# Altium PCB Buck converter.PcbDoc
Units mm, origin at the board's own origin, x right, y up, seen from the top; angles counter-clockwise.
Board outline 85.72 x 66.93 mm, 2 copper layers (Top Layer, Bottom Layer); 24 components, 13 nets, 75 pads, 15 vias.
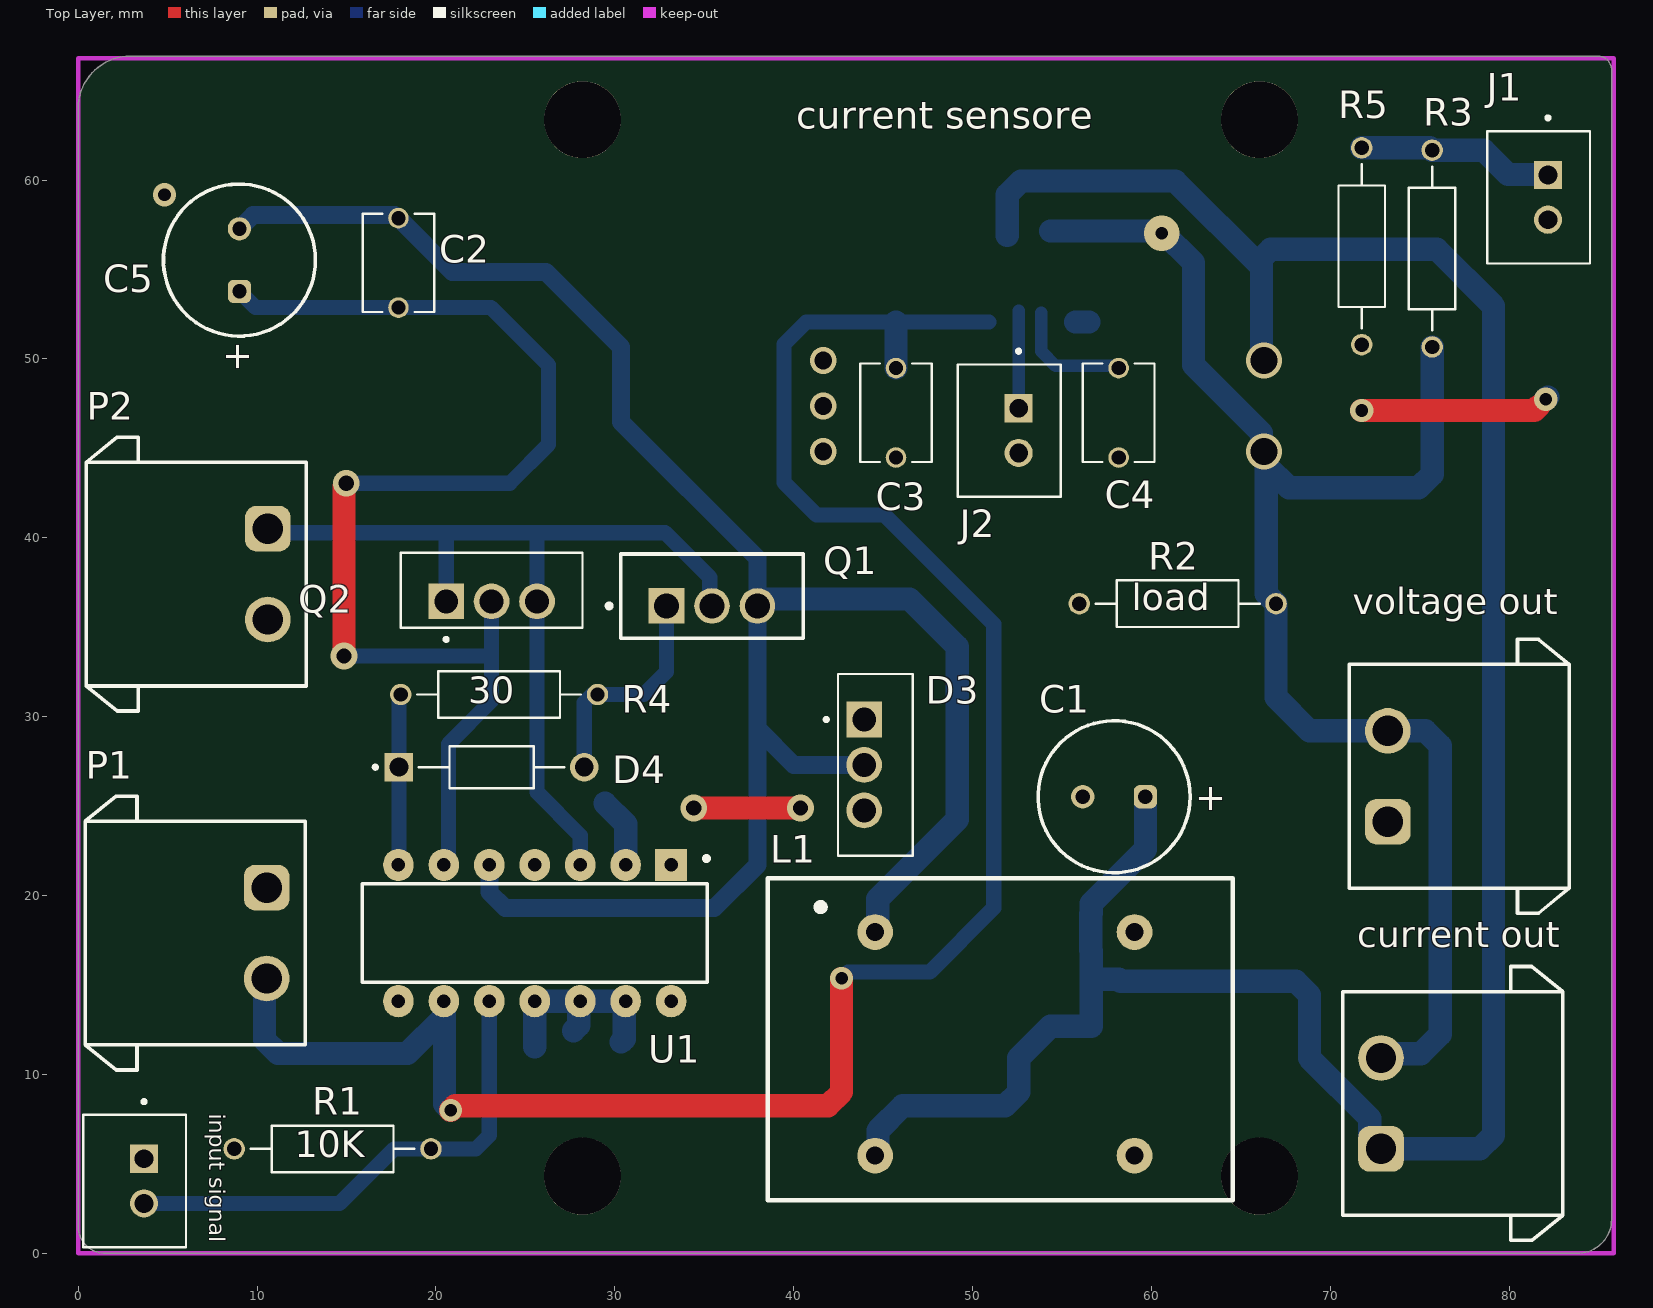
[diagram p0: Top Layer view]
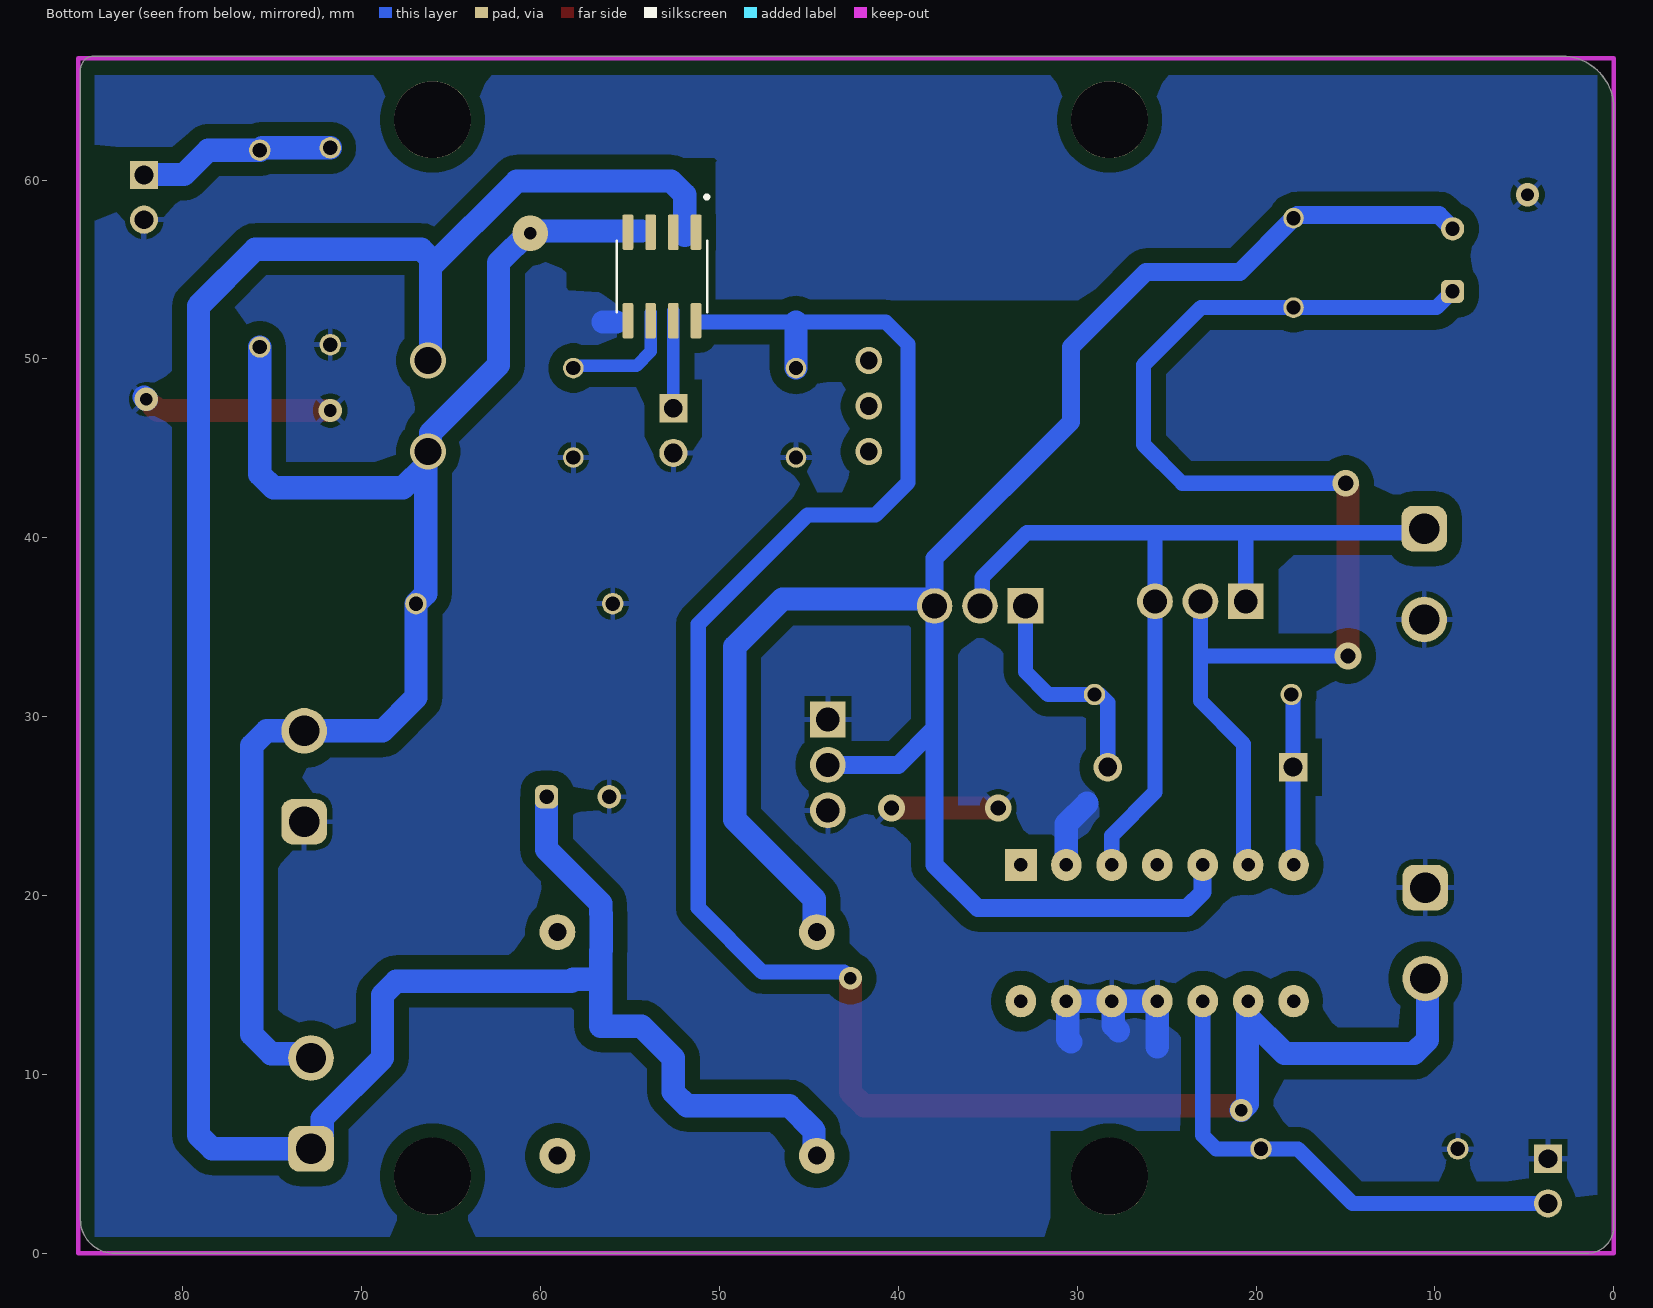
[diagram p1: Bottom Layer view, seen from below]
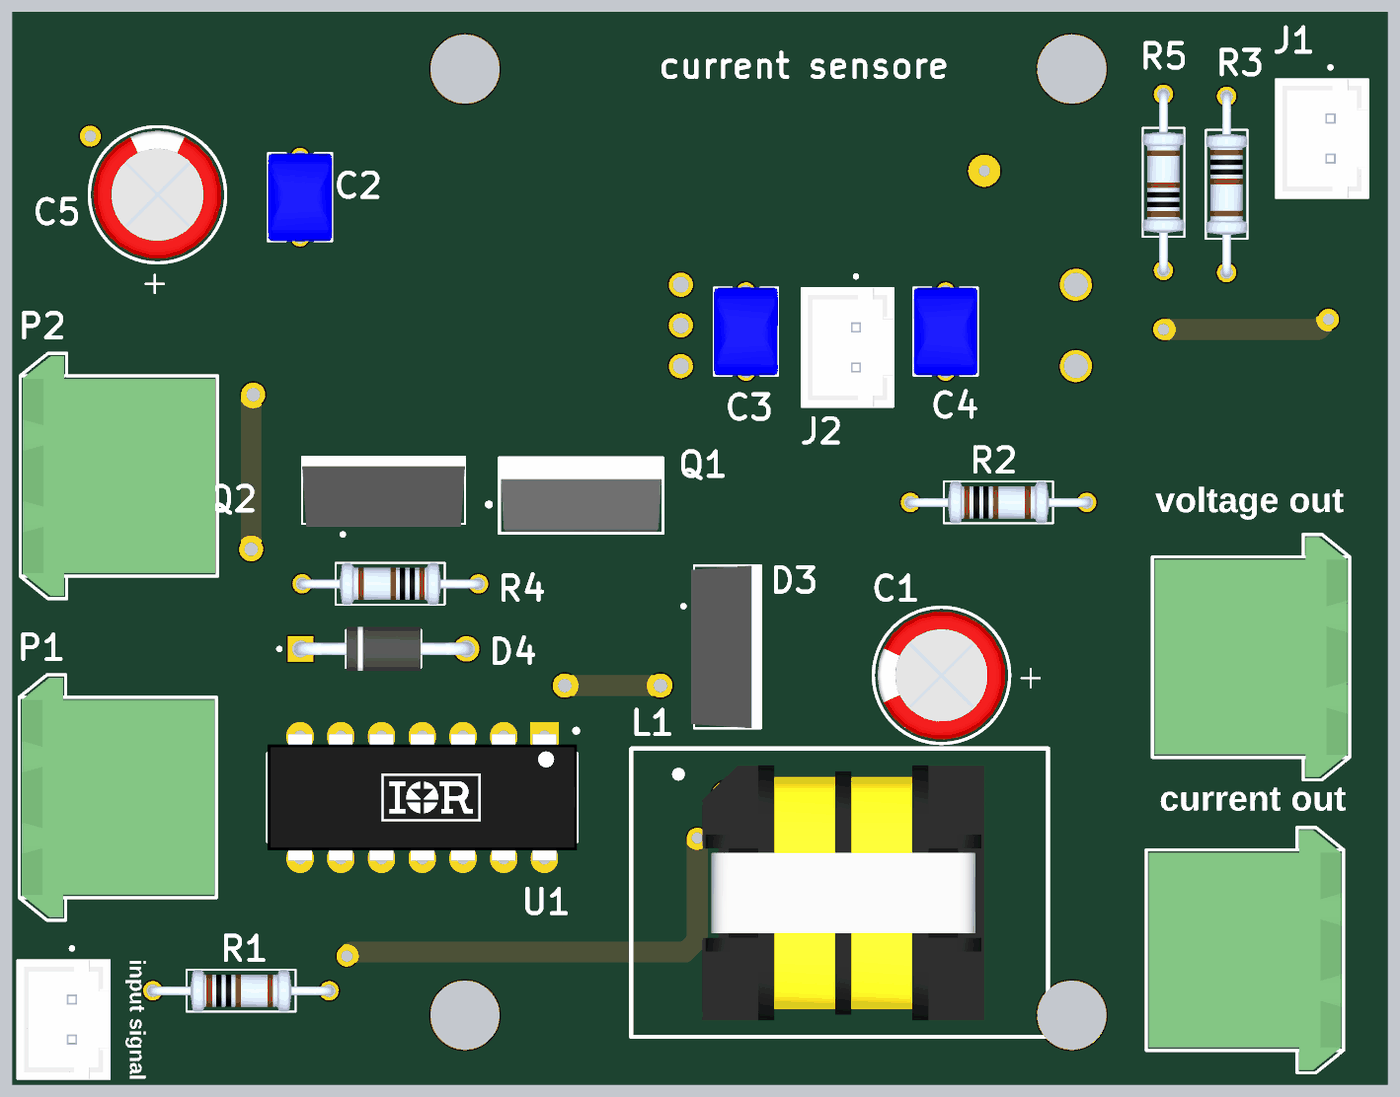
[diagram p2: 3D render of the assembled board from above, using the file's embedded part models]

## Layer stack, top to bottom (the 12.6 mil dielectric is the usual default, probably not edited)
Top Solder: solder mask 0.0102, Solder Resist, Dk 3.5
Top Layer: signal copper 0.0356
Dielectric 1: dielectric 0.32, FR-4, Dk 4.8
Bottom Layer: signal copper 0.0356
Bottom Solder: solder mask 0.0102, Solder Resist, Dk 3.5

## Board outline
0,1.524 0,64.008 cw(c2.921,64.008) 2.921,66.929 84.963,66.929 cw(c84.963,66.167) 85.725,66.167 85.725,1.905 cw(c83.82,1.905) 83.82,0 1.524,0 cw(c1.524,1.524)

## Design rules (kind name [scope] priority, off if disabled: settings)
Clearance [All] p1: gap=0.8 ignorepadtopadclearanceinfootprint=FALSE
PolygonConnect PolygonConnect_6 [All vs IsNamedPolygon('NONET_L-01_P-001')] p1: thpad.connectstyle=Relief thpad.reliefconductorwidth=0.3 thpad.reliefentries=4 thpad.polygonreliefangle="90 Angle" thpad.airgapwidth=0.3 smdpad.connectstyle=Relief smdpad.reliefconductorwidth=0.3 smdpad.reliefentries=4 smdpad.polygonreliefangle="45 Angle" smdpad.airgapwidth=0.3 via.connectstyle=Relief via.reliefconductorwidth=0.3 via.reliefentries=4 via.polygonreliefangle="45 Angle" via.airgapwidth=0.3
PolygonConnect PolygonConnect_5 [All vs IsNamedPolygon('NONET_L-01_P-001')] p2: thpad.connectstyle=Relief thpad.reliefconductorwidth=0.3 thpad.reliefentries=4 thpad.polygonreliefangle="45 Angle" thpad.airgapwidth=0.254 smdpad.connectstyle=Relief smdpad.reliefconductorwidth=0.254 smdpad.reliefentries=4 smdpad.polygonreliefangle="90 Angle" smdpad.airgapwidth=0.254 via.connectstyle=Relief via.reliefconductorwidth=0.254 via.reliefentries=4 via.polygonreliefangle="90 Angle" via.airgapwidth=0.254
PolygonConnect PolygonConnect_4 [All vs IsNamedPolygon('NONET_L-01_P-001')] p3: connectstyle=Relief reliefconductorwidth=0.254 reliefentries=4 polygonreliefangle="90 Angle" airgapwidth=0.15
PolygonConnect PolygonConnect_3 [All vs IsNamedPolygon('NONET_L-01_P-001')] p4: connectstyle=Relief reliefconductorwidth=0.254 reliefentries=4 polygonreliefangle="90 Angle" airgapwidth=0.254
PolygonConnect PolygonConnect_2 [All vs IsNamedPolygon('NONET_L-01_P-001')] p5: connectstyle=Direct reliefconductorwidth=0.254 reliefentries=4 polygonreliefangle="90 Angle" airgapwidth=0.254
PolygonConnect PolygonConnect_1 [All vs IsNamedPolygon('GND_L02_P000')] p6: connectstyle=Direct reliefconductorwidth=0.254 reliefentries=4 polygonreliefangle="90 Angle" airgapwidth=0.254
PolygonConnect [All] p7: connectstyle=Relief reliefconductorwidth=0.254 reliefentries=4 polygonreliefangle="90 Angle" airgapwidth=0.254
RoutingVias [All] p1: holewidth=0.711 width=1.27 viastyle="Through Hole" minholewidth=0.711 minwidth=1.27 maxholewidth=0.711 maxwidth=1.27
SolderMaskExpansion [All] p1: expansion=0.102 istentingtop=FALSE
SupplyNets "Schematic Supply Nets_10" [InNet('+5')] p1: voltage=0.000
SupplyNets "Schematic Supply Nets_9" [InNet('VCC')] p2: voltage=0.000
SupplyNets "Schematic Supply Nets_8" [InNet('GND')] p3: voltage=0.000
Width [All] p1: maxlimit=1.5 minlimit=1.2 preferedwidth=1.3 minimp=50.000000 maximp=50.000000 favimp=50.000000
30 further rules are at their usual default settings.

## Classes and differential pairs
component class "Buck converter": C1 C2 C3 C4 C5 "current out" D3 D4 "input signal" J1 L1 P1 P2 Q1 Q2 R1 R2 R3 R4 R5 U1 "voltage out"

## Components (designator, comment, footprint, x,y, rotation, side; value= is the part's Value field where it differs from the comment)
C1 "22uf cap" "cap 22uf 50V" 57.912,25.527 r0 top
C2 "cap 0.1uf" "CAP ceramic" 17.907,55.372 r90 top
C3 "cap 100nf" "CAP ceramic" 45.72,46.99 r90 top
C4 "cap 1nf" "CAP ceramic" 58.166,46.99 r270 top
C5 "220uf cap" "cap 22uf 50V" 9.017,55.527 r270 top
"current out" "691305540002" "Horizontal Pluggable" 76.835,8.382 r90 top
D3 "MBR20100CT" TO254P1066X482X2286-3 43.942,29.845 r270 top
D4 "1N5820" 1N4007 23.114,27.178 r0 top
"input signal" "JST_B2B vertical pins" "JST_B2B vertical pins" 3.158,4.044 r90 top
J1 "JST_B2B vertical pins" "JST_B2B vertical pins" 81.644,59.035 r90 top (schematic designator J?)
J2 "JST_B2B vertical pins" "JST_B2B vertical pins" 52.053,45.994 r90 top (schematic designator J?)
L1 "2mH E shape" "2mH E shape" 44.555,17.961 r0 top value=2mH
P1 "691305540002" "Horizontal Pluggable" 6.541,17.907 r270 top
P2 "691305540002" "Horizontal Pluggable" 6.604,37.973 r270 top
Q1 "IRLZ44N" IFX-PG-TO220-3-904-1 35.433,36.195 r0 top
Q2 "U10A6CIC" TO254P1066X482X2286-3 20.574,36.449 r0 top
R1 "10k" RES 14.224,5.842 r0 top
R2 "load" RES 61.468,36.322 r0 top
R3 "30K" RES 75.692,56.173 r270 top
R4 "30" RES 23.534,31.242 r180 top
R5 "7.5K" RES 71.755,56.3 r90 top
U1 "IR2110" DIP762W46P254L1930H533Q14B 25.527,17.907 r270 top
U2 "ACS712" SOIC127P600X175-8N 53.213,54.61 r270 bottom
"voltage out" "691305540002" "Horizontal Pluggable" 77.216,26.67 r90 top

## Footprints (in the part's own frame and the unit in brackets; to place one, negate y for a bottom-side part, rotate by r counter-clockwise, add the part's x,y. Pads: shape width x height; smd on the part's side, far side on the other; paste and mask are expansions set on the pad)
1N4007 [mm]
  round 1.59 hole 1.06 mask+0.102: A(5.18,0)
  rect 1.59x1.59 / inner round 1.59 / far side rect 1.59x1.59 hole 1.06 mask+0.102: C(-5.18,0)
  silkscreen extent -6.6,-1.17 4.07,1.17, body extent -5.57,-1.36 5.57,1.36, height 2.72
"2mH E shape" [mm]
  round 2 hole 1: 1(0,0) 2(0,-12.5) 3(14.5,0) 4(14.5,-12.5)
  silkscreen extent -6,-15 20,3, body extent -1.56,-13.97 16.04,1.93, height 18.9
"cap 22uf 50V" [mm] "Aluminum Electrolytic Capacitors, 8x11.5mm"
  rrect50% 1.3x1.3 hole 0.8: 1(1.75,0)
  round 1.3 hole 0.8: 2(-1.75,0)
  silkscreen extent -4.25,-4.25 4.25,4.25, body extent -3.99,-4 4,4, height 11.81
"CAP ceramic" [mm]
  round 1.15 hole 0.8: 1(-2.5,0) 2(2.5,0)
  silkscreen extent -2.75,-2 2.75,2, body extent -2.75,-2 2.75,2, height 7
DIP762W46P254L1930H533Q14B [mm] "DIP,7.62mm lead span,2.54mm pitch;14 pin,6.605mm W X 19.305mm L X 5.33mm H body"
  rect 1.8x1.8 hole 0.75 paste-2539.97 mask+0: 1(-3.81,7.62)
  oval 1.8x1.7 hole 0.75 paste-2539.97 mask+0: 2(-3.81,5.08) 3(-3.81,2.54) 4(-3.81,0) 5(-3.81,-2.54) 6(-3.81,-5.08) 7(-3.81,-7.62) 8(3.81,-7.62) 9(3.81,-5.08) 10(3.81,-2.54) 11(3.81,0) 12(3.81,2.54) 13(3.81,5.08) 14(3.81,7.62)
  silkscreen extent -4.29,-9.65 2.75,9.73, body extent -3.96,-9.65 3.96,9.65, height 5.33
"Horizontal Pluggable" [mm] "5,08mm - PCB Header Horizontal Entry with Plastic Latches - 02p"
  rrect50% 2.55x2.55 hole 1.7: 1(-2.54,4)
  round 2.55 hole 1.7: 2(2.54,4)
  silkscreen extent -7.65,-6.15 7.65,6.15, body extent -7.48,-6 7.48,6, height 8.63
IFX-PG-TO220-3-904-1 [mm] "TO,flange mount,2.54 mm pitch, 3 pin, 10.16 mm L X 4.57 mm W X 20.56 mm H body"
  rect 1.99x1.99 hole 1.39 paste-2539.97 mask+0: 1(-2.54,0)
  round 1.99 hole 1.39 paste-2539.97 mask+0: 2(0,0) 3(2.54,0)
  silkscreen extent -5.87,-1.8 5.1,2.9, body extent -5.16,-1.72 5.16,2.86, height 19.84
"JST_B2B vertical pins" [mm]
  rect 1.575x1.575 / inner round 1.575 / far side rect 1.575x1.575 hole 1.05: 1(1.25,-0.525)
  round 1.575 hole 1.05: 2(-1.25,-0.525)
  silkscreen extent -3.7,-2.88 4.54,2.88, body extent -3.7,-2.88 3.7,2.88, height 7
RES [mm]
  round 1.2 hole 0.8: 1(-5.5,0) 2(5.5,0)
  silkscreen extent -4.58,-1.3 4.58,1.3, body extent -5.77,-1.3 5.77,1.3, height 2.6
SOIC127P600X175-8N [mm]
  rrect25% 1.97x0.6 smd paste+0 mask+0.102: 1(-2.475,1.905) 2(-2.475,0.635) 3(-2.475,-0.635) 4(-2.475,-1.905) 5(2.475,-1.905) 6(2.475,-0.635) 7(2.475,0.635) 8(2.475,1.905)
  silkscreen extent -4.54,-2.52 2,2.6, body extent -3,-2.45 3,2.45, height 1.75
TO254P1066X482X2286-3 [mm]
  rect 2x2 / inner round 2 / far side rect 2x2 hole 1.33: 1(0,0)
  round 2 hole 1.33: 2(2.54,0) 3(5.08,0)
  silkscreen extent -2.54,-2.22 7.62,2.72, body extent -2.54,-1.65 7.62,2.7, height 20.4

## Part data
C1: "CAP ALUM 22UF 20% 400V RADIAL", Package="RADIAL-2 Panasonic"
C2 C3 C4: library part "cap 100nF", "Capacitor, Ceramic, 100nF, 100VDC, 10-% Tol, 10+% Tol, X7R-TC Code, -15, 15%-TC", Package="Radial AVX"
C5: library part "22uf cap", "CAP ALUM 22UF 20% 400V RADIAL", Package="RADIAL-2 Panasonic"
"current out" P1 P2 "voltage out": library part "horizontal Pluggable", "WR-TBL Series 3055 PCB Header Horizontal Entry with Plastic Latches, THT, pitch 5.08mm, 2p", Manufacturer="Wurth Elektronik", Operating Temperature Max=105°C, Operating Temperature Min=-40°C, Rated Current=16A, Working Voltage=300V
D3: "Diode Array 1 Pair Common Cathode Schottky 100 V 10A Through Hole TO-262-3 Long Leads, IÂ²Pak, TO-262AA", Package="TO-220-3 ON Semiconductor"
D4: library part 1N4007, "Diode, DO-41, 1000V, 1A, 175Â°C", Package="DO-41 Diotec"
"input signal" J1 J2: "Connector Header Through Hole 2 position 0.098 (2.50mm)", Package=None
L1: library part CMP-006-00023-3
Q1: "OptiMOS 3 Power-Transistor, VDS 100V", Manufacturer="Infineon Technologies"
Q2: library part "Diode U10A6CIC", "Ultra Fast Recovery Rectifier Diode 600V 10A", Package="TO-220-3 Vishay"
R1 R2 R3 R5: library part RES, "1.07 kOhms Â±1% 0.25W, 1/4W Through Hole Resistor Axial - Metal Film", Package="Axial Yageo"
R4: library part RES, Package="Axial Yageo"
U1: "High and Low Side Driver", Manufacturer="Infineon Technologies"
U2: "Fully Integrated, Hall-Effect-Based Linear Current Sensor IC with 2.4 kVRMS Isolation and a Low-Resistance Current Conductor", Package=None

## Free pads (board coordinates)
  round 4.3 hole 4.3: 1(28.194,63.373) 2(28.194,4.318) 3(66.04,63.373) 4(66.04,4.318)

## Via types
v1: diameter 1.5, hole 0.85, Top Layer to Bottom Layer, 4 vias
v2: diameter 1.3, hole 0.711, Top Layer to Bottom Layer, 3 vias
v3: diameter 1.5, hole 1, Top Layer to Bottom Layer, 3 vias
v4: diameter 2, hole 1.5, Top Layer to Bottom Layer, 2 vias
v5: diameter 2, hole 0.7, Top Layer to Bottom Layer, 1 vias
v6: diameter 1.27, hole 0.711, Top Layer to Bottom Layer, 1 vias
v7: diameter 1.27, hole 0.7, Top Layer to Bottom Layer, 1 vias

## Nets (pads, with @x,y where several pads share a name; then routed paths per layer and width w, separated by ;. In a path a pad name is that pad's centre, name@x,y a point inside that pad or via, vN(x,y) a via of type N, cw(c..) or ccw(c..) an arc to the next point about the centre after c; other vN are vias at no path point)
+5: C3.2 P1.2 U1.9 U2.8 | length 112.8
  Top Layer w1.3: v6(20.828,8.001) 21.082,8.255 41.916,8.255 42.677,9.017 v7(42.677,15.372)
  Bottom Layer w0.85: v7(42.677,15.372) 43.041,15.736 47.613,15.736 51.181,19.304 51.181,35.179 45.085,41.275 41.275,41.275 39.456,43.094 39.456,50.822 40.704,52.07 45.72,52.07 50.927,52.07
  Bottom Layer w1.3: P1.2 10.414,15.24 10.414,11.938 11.176,11.176 18.415,11.176 20.409,13.17 ; U1.9 20.485,14.059 20.485,8.344 v6(20.828,8.001) ; C3.2 45.72,52.07
GND: "input signal.1" "voltage out.1" C1.2 C3.1 C4.2 D3.1 D3.3 J1.2 J2.2 P1.1 P2.2 R1.1 R2.1 R5.1 U1.2 U1.11 U1.12 U1.13 U2.5 | length 32.7
  Top Layer w1.3: v1(34.417,24.892) v1(40.386,24.892) ; v2(71.755,47.117) 81.407,47.117 v2@81.661,47.371
  Bottom Layer w1.3: 25.527,11.557 U1.11 U1.12 ; 27.686,12.446 27.99,12.75 27.99,14.02 U1.12 ; 29.45,25.16 30.607,24.003 U1.2 ; 30.353,11.811 30.53,11.988 30.53,14.02 U1.13 U1.12 ; 55.753,52.07 56.515,52.07 ; v2(82.042,47.752) v2@82.169,47.879
  other v2: 4.826,59.182
HO: D4.C R4.2 U1.7 | length 9.5
  Bottom Layer w0.85: R4.2@17.967,31.08 17.934,31.047 17.934,22.12 18.161,21.893 U1.7@18.161,21.717
IP+_1: "current out.1" C1.1 L1.2 U2.1 U2.2 | length 145.8
  Bottom Layer w1.3: L1.2@44.704,5.461 44.689,5.476 44.689,6.09 44.717,6.118 44.717,6.871 46.101,8.255 51.816,8.255 52.578,9.017 52.578,10.922 54.356,12.7 56.642,12.7 56.642,15.319 ; 51.943,56.896 51.943,59.182 52.705,59.944 61.337,59.944 66.16,55.121 ; C1.1 59.662,22.578 56.642,19.558 56.642,19.013 56.605,18.976 56.605,16.946 56.642,16.909 56.642,15.319 ; v4(66.294,49.911) 66.16,50.045 66.16,52.585 66.16,55.121 ; 56.642,15.319 58.17,15.319 58.28,15.209 68.072,15.209 68.834,14.447 68.834,10.922 72.21,7.546 72.21,6.467 72.835,5.842 78.359,5.842 79.121,6.604 79.121,52.959 75.946,56.134 66.675,56.134 66.16,55.619 66.16,55.121
IP-_1: "current out.2" "voltage out.2" R2.2 R3.2 U2.3 U2.4 | length 83.3
  Bottom Layer w1.3: 54.356,57.15 55.118,57.15 60.579,57.15 62.357,55.372 62.357,49.657 66.16,45.854 66.16,44.965 v4(66.294,44.831) ; 72.835,10.922 73.074,11.161 75.057,11.161 76.141,12.245 76.141,28.38 75.311,29.21 73.216,29.21 68.834,29.21 66.968,31.076 R2.2 66.421,36.869 66.421,44.831 v4(66.294,44.831) ; R3.2 75.692,43.561 74.93,42.799 67.691,42.799 66.428,44.062 66.428,44.697 v4(66.294,44.831)
  other v5: 60.579,57.023
NetC4_1: C4.1 U2.6 | length 6.8
  Bottom Layer w0.7: U2.6@53.848,52.578 U2.6 53.848,50.419 54.65,49.617 C4.1@58.166,49.617
NetD4_A: D4.A Q1.1 R4.1 | length 12.6
  Bottom Layer w0.85: D4.A 28.294,30.795 28.741,31.242 31.623,31.242 32.893,32.512 Q1.1
PWM: "input signal.2" R1.2 U1.10 | length 28.4
  Bottom Layer w0.85: 3.683,2.794 14.605,2.794 17.653,5.842 R1.2 22.225,5.842 22.987,6.604 U1.10
VB: C2.1 C5.1 Q2.2 U1.6 | length 69.6
  Top Layer w1.3: v1(14.859,33.401) 14.859,42.872 14.986,42.999 v1(14.986,43.053)
  Bottom Layer w0.85: C5.1 9.922,52.872 C2.1 23.074,52.872 26.289,49.657 26.289,45.212 24.13,43.053 v1(14.986,43.053) ; v1(14.859,33.401) 23.114,33.401 ; U1.6@20.701,21.47 20.701,28.481 23.114,30.894 23.114,33.401 ; Q2.2 23.114,33.401
VCC: P2.1 Q1.2 Q2.1 Q2.3 U1.3 | length 51.1
  Bottom Layer w0.85: P2.1 10.829,40.288 20.574,40.288 ; Q2.1 20.574,40.288 ; U1.3 28.067,23.368 25.654,25.781 Q2.3 25.654,40.161 25.527,40.288 ; Q1.2@35.313,36.075 Q1.2 35.313,36.315 35.313,37.78 32.805,40.288 25.527,40.288 ; 20.574,40.288 25.527,40.288
"Vout arduino 1": J2.1 U2.7 | length 5.5
  Bottom Layer w0.7: J2.1 U2.7 U2.7@52.578,52.705
"Vout arduino 2": J1.1 R3.1 R5.2 | length 11
  Bottom Layer w1.3: R5.2 75.565,61.8 R3.1 78.573,61.673 79.941,60.305 82.149,60.305 J1.1
VS: C2.2 C5.2 D3.2 L1.1 Q1.3 U1.5 | length 111.7
  Bottom Layer w1: C5.2 9.779,58.039 17.699,58.039 17.866,57.872 C2.2 20.915,54.864 26.162,54.864 30.353,50.673 30.353,46.482 37.973,38.862 37.973,36.576 Q1.3 37.973,29.337 ; U1.5 22.987,20.193 23.876,19.304 35.56,19.304 37.973,21.717 37.973,29.337 ; D3.2 40.005,27.305 37.973,29.337
  Bottom Layer w1.3: Q1.3 38.16,36.195 38.541,36.576 46.482,36.576 49.149,33.909 49.149,24.257 44.704,19.812 44.704,18.605 44.689,18.59 L1.1@44.689,17.976
pads on no net: L1.3 L1.4 U1.1 U1.4 U1.8 U1.14
copper on no net:
  other v3: 41.656,44.831 41.656,47.371 41.656,49.911

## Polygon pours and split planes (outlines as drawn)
GND on Bottom Layer "NONET_L-01_P-001" (solid, remove dead copper, pour order 0): 0,66.802 0.127,66.929 85.725,66.929 85.725,-0.127 85.344,0.254 0,0.254

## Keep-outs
Keep-Out Layer:
  lines w0.254: 0,0 85.852,0 85.852,66.802 0,66.802 0,0

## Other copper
Bottom Layer:
  pour cut-out: 24.257,6.858 31.496,6.858 31.496,0.381
  pour cut-out: 50.244,53.306 50.244,61.008 50.165,61.087 50.292,61.214 58.547,61.214 58.547,53.975 58.42,53.848
  pour cut-out: 40.384,53.263 29.959,53.263 29.845,53.149 29.845,52.578
  pour cut-out: 40.259,53.213 29.845,53.213 29.845,53.086

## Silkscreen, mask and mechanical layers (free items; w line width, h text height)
Top Overlay:
  text "current sensore" at 40.132,62.865 h1.52
  text "load" at 58.903,35.459 h2.54
  text "30" at 21.822,30.257 h2.54
  text "10K" at 12.105,4.857 h2.54
Bottom Component Outline:
  lines w0.254: 85.725,0.127 85.852,0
